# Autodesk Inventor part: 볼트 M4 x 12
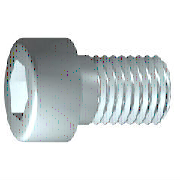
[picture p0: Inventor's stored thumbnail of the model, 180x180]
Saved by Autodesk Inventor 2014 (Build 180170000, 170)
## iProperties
IsCustomPart: 1
Created: 2012-02
Part Number: 볼트 M4 x 12
Material: 스테인리스강
Description: 6각 소켓 머리 캡 나사
Document SubType Name: Modeling
Standard: ISO 4762
Designer: mduedu
Standard Revision: Fourth edition 2004-03-01
Standards Organization: ISO
Language: ko-KR
Size Designation: M4 x 12
Categories: <MemberInstance><Categories><Category DisplayName="조임쇠" InternalName="e4da775c-781d-43d5-af7c-5136215cf5a6" Mnemonic="FSTN"><Category DisplayName="볼트" InternalN
Density: 8.08 g/cm^3
Mass: 2.2972 g
Surface Area: 3.30853 cm^2
Volume: 0.284306 cm^3
Appearance: 반광택
Author: mduedu
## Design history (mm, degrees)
sketch "스케치1"
  geometry: L1 (-1, 0)-(12, 0); L2 (12, 0)-(12, 2); L3 (12, 2)-(1.75, 2); L4 (1.75, 2)-(1.32, 2); L5 (1.32, 2)-(0, 2); L6 (0, 2)-(0, 3.5); L7 (0, 3.5)-(-4, 3.5); L8 (-4, 3.5)-(-4, 1.732); L9 (-4, 1.732)-(-2, 1.732); L10 (-2, 1.732)-(-1, 0); L11 (-7.2, 0)-(15.2, 0) reference; L12 (0, -0.7)-(0, 4.2) reference; L13 (1.75, 2)-(0, 2)
  constraints: 22 end point, 6 parallel, 2 collinear, 2 perpendicular, 1 horizontal, 1 point on line
  dimensions: "d1" = 10.25 distance from line of L3.end L2 (= GEL); "d2" = 0.42952 distance of L4.end L3.end (computed from GAL); "d3" = 4 distance between parallel lines of L8 L6 (= KOH); "d4" = 2 distance of L8.end L9.end (= INTI); "d5" = 60 deg angle of L10 L1; "d6" = 4 diameter of L3 L1 (= GD); "d7" = 4 diameter of L5 L1 (= BDM); "d8" = 3.4641 diameter of L9 L1 (= 1.1547 x SW); "d9" = 7 diameter of L7 L1 (= KOD); "d26" = 12 distance between parallel lines of L12 L2 (= NLG)
revolve "본체" sketch "스케치1" stored, may be unused: angle "d10" = 90 deg
sketch "스케치2"
  geometry: L1 (0, -4.9)-(0, 4.9) reference; L2 (-4.9, 0)-(4.9, 0) reference; L3 (1.732, 0)-(0.866, -1.5); L4 (0.866, -1.5)-(-0.866, -1.5); L5 (-0.866, -1.5)-(-1.732, 0); L6 (-1.732, 0)-(-0.866, 1.5); L7 (-0.866, 1.5)-(0.866, 1.5); L8 (0.866, 1.5)-(1.732, 0); 2 further points
  constraints: 12 end point, 1 coincident, 1 horizontal alignment, 1 point on line, 12 other
extrude "슬롯" join sketch "스케치2" stored distance "d11" = 10; taper "d12" = 0 deg
workplane "Work Plane1"
fillet "Fillet2" dims "d30" = 0.1 (= R)
body "Solid1"
fillet "모깎기1" dims "d17" = 0.4 (= RR)
feature "스레드" dims "d13" = 10.25 (= GEL), "d14" = 0
chamfer "모따기1" distance "d15" = 0.42941 (= -0.5 x SPD + 0.5 x GD); stored, may be unused: second distance "d16" = 0.42941 (= GUL), angle "d27" = 45 deg
other parameters: "GD" = 4 [user parameter; used in 2 equation terms], "NLG" = 12 [user parameter; used in 1 equation term], "GEL" = 10.25 [user parameter; used in 2 equation terms], "KOD" = 7 [user parameter; used in 1 equation term], "KOH" = 4 [user parameter; used in 1 equation term], "INTI" = 2 [user parameter; used in 1 equation term], "GAL" = 0.42941 (= 0.61345 x PTC) [user parameter; used in 1 equation term], "GUL" = 0.42941 (= 0.61345 x PTC) [user parameter; used in 1 equation term], "BDM" = 4 (= NND) [user parameter; used in 1 equation term], "SW" = 3 [user parameter; used in 2 equation terms], "RR" = 0.4 [user parameter; used in 1 equation term], "SPD" = 3.14117 (= NND - 1.2269 x PTC) [user parameter; used in 1 equation term], "d19" = 0, "d28" = 0, "d29" = 0, "R" = 0.1 [user parameter; used in 1 equation term], "TOA" = 30 deg [user parameter], "GD1" = 3.14117 (= THREADDIA - 1.2269 x PTC) [user parameter], "THREADDIA" = 4 [user parameter; used in 1 equation term], "FAWI" = 45 deg [user parameter], "TPU" = 14.28571 (computed from PTC) [user parameter], "PTC" = 0.7 [user parameter; used in 5 equation terms], "NND" = 4 [user parameter; used in 2 equation terms], "E0" = 3.465 (= 1.155 x SW) [user parameter]
